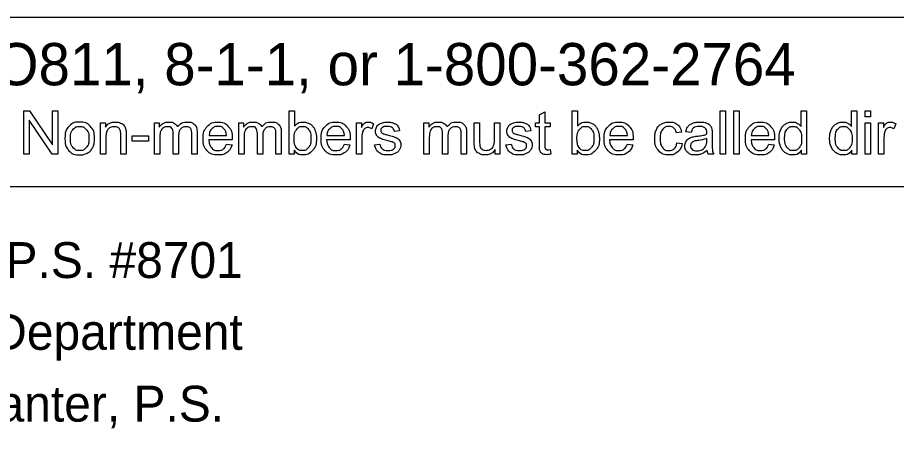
# Model space of a CAD drawing. Extents: x 0 to 34, y 0 to 22.
# Drawn here: x 27.662 to 31.093, y 11.056 to 12.674 of the extents above; entities that cross this region are included whole.
import ezdxf

# ---------------------------------------------------------------- set-up
doc = ezdxf.new("R2010")
doc.units = 0
doc.layers.add('SH_Data', color=7, linetype='Continuous')
doc.layers.add('SH_Text', color=7, linetype='Continuous')

msp = doc.modelspace()

# ---------------------------------------------------------------- linework, layer by layer
at = {"layer": 'SH_Data'}
for p, q in [((32.2439, 12.674), (27.0189, 12.674)), ((32.2439, 12.014), (27.0189, 12.014))]:
    msp.add_line(p, q, dxfattribs=at)
for points in [[(27.6862, 12.1409), (27.6862, 12.3103), (27.7091, 12.3103), (27.7983, 12.1772), (27.7983, 12.3103), (27.8197, 12.3103), (27.8197, 12.1409), (27.7968, 12.1409), (27.7076, 12.2739), (27.7076, 12.1409), (27.6862, 12.1409)], [(28.7416, 12.1409), (28.7224, 12.1409), (28.7224, 12.3103), (28.7431, 12.3103), (28.7431, 12.2499)], [(29.6994, 12.1768), (29.6994, 12.2475), (29.684, 12.2475), (29.684, 12.2637), (29.6994, 12.2637), (29.6994, 12.2941), (29.7202, 12.3065), (29.7202, 12.2637), (29.7409, 12.2637), (29.7409, 12.2475), (29.7202, 12.2475), (29.7202, 12.1756)], [(29.8462, 12.1409), (29.8269, 12.1409), (29.8269, 12.3103), (29.8477, 12.3103), (29.8477, 12.2499)], [(30.4054, 12.1409), (30.4054, 12.3103), (30.4262, 12.3103), (30.4262, 12.1409), (30.4054, 12.1409)], [(30.4579, 12.1409), (30.4579, 12.3103), (30.4787, 12.3103), (30.4787, 12.1409), (30.4579, 12.1409)], [(30.7207, 12.2496), (30.7207, 12.3103), (30.7415, 12.3103), (30.7415, 12.1409), (30.7222, 12.1409)], [(30.918, 12.2496), (30.918, 12.3103), (30.9388, 12.3103), (30.9388, 12.1409), (30.9195, 12.1409)], [(30.9716, 12.2864), (30.9716, 12.3103), (30.9923, 12.3103), (30.9923, 12.2864), (30.9716, 12.2864)], [(27.9863, 12.1409), (27.9863, 12.2637), (28.005, 12.2637), (28.005, 12.2462)], [(28.1966, 12.1409), (28.1966, 12.2637), (28.2152, 12.2637), (28.2152, 12.2463)], [(28.5253, 12.1409), (28.5253, 12.2637), (28.5439, 12.2637), (28.5439, 12.2463)], [(28.9854, 12.1409), (28.9854, 12.2637), (29.0041, 12.2637), (29.0041, 12.2451)], [(29.052, 12.2597), (29.0447, 12.2405)], [(29.2485, 12.1409), (29.2485, 12.2637), (29.2671, 12.2637), (29.2671, 12.2463)], [(29.4451, 12.1876), (29.4451, 12.2637), (29.4659, 12.2637), (29.4659, 12.1956)], [(29.5238, 12.1979), (29.5238, 12.2637), (29.5446, 12.2637), (29.5446, 12.1409), (29.526, 12.1409)], [(30.9716, 12.1409), (30.9716, 12.2637), (30.9923, 12.2637), (30.9923, 12.1409), (30.9716, 12.1409)], [(31.0237, 12.1409), (31.0237, 12.2637), (31.0424, 12.2637), (31.0424, 12.2451)], [(31.0903, 12.2597), (31.0831, 12.2405)], [(28.0859, 12.2163), (28.0859, 12.1409), (28.0652, 12.1409), (28.0652, 12.2155)], [(28.2903, 12.2122), (28.2903, 12.1409), (28.2695, 12.1409), (28.2695, 12.2206)], [(28.363, 12.2251), (28.363, 12.1409), (28.3422, 12.1409), (28.3422, 12.2182)], [(28.619, 12.2122), (28.619, 12.1409), (28.5983, 12.1409), (28.5983, 12.2206)], [(28.6917, 12.2251), (28.6917, 12.1409), (28.6709, 12.1409), (28.6709, 12.2182)], [(29.1535, 12.2319), (29.1331, 12.2292)], [(29.3422, 12.2122), (29.3422, 12.1409), (29.3214, 12.1409), (29.3214, 12.2206)], [(29.4149, 12.2251), (29.4149, 12.1409), (29.3941, 12.1409), (29.3941, 12.2182)], [(29.6663, 12.2319), (29.6459, 12.2292)], [(30.2546, 12.2275), (30.2343, 12.2244)], [(30.2912, 12.2258), (30.2708, 12.2286)], [(30.3736, 12.22), (30.3736, 12.1923)], [(28.0071, 12.2079), (28.0071, 12.1409), (27.9863, 12.1409)], [(28.1096, 12.1918), (28.1096, 12.2127), (28.1736, 12.2127), (28.1736, 12.1918), (28.1096, 12.1918)], [(28.2174, 12.2045), (28.2174, 12.1409), (28.1966, 12.1409)], [(28.4998, 12.1969), (28.4082, 12.1969)], [(28.4094, 12.214), (28.4779, 12.214)], [(28.4777, 12.1805), (28.4992, 12.1778)], [(28.5461, 12.2045), (28.5461, 12.1409), (28.5253, 12.1409)], [(28.9601, 12.1969), (28.8685, 12.1969)], [(28.8697, 12.214), (28.9382, 12.214)], [(28.938, 12.1805), (28.9595, 12.1778)], [(29.0061, 12.2052), (29.0061, 12.1409), (28.9854, 12.1409)], [(29.056, 12.1776), (29.0765, 12.1808)], [(29.2693, 12.2045), (29.2693, 12.1409), (29.2485, 12.1409)], [(29.5688, 12.1776), (29.5894, 12.1808)], [(30.0647, 12.1969), (29.9731, 12.1969)], [(29.9743, 12.214), (30.0428, 12.214)], [(30.0426, 12.1805), (30.0641, 12.1778)], [(30.2361, 12.1858), (30.2565, 12.1831)], [(30.3526, 12.1949), (30.3527, 12.2025)], [(30.617, 12.1969), (30.5255, 12.1969)], [(30.5266, 12.214), (30.5952, 12.214)], [(30.5949, 12.1805), (30.6164, 12.1778)], [(31.0445, 12.2052), (31.0445, 12.1409), (31.0237, 12.1409)], [(28.7416, 12.1563), (28.7416, 12.1409)], [(29.526, 12.1409), (29.526, 12.159)], [(29.7409, 12.1594), (29.7439, 12.141)], [(29.8462, 12.1563), (29.8462, 12.1409)], [(30.7222, 12.1409), (30.7222, 12.1564)], [(30.9195, 12.1409), (30.9195, 12.1564)], [(30.3802, 12.1409), (30.3585, 12.1409)]]:
    msp.add_lwpolyline(points, dxfattribs=at)
for points, degree in [([(27.8469, 12.2023), (27.8469, 12.2364), (27.8659, 12.2528), (27.8817, 12.2664), (27.9045, 12.2664), (27.9298, 12.2664), (27.9458, 12.2498), (27.9619, 12.2332), (27.9619, 12.204), (27.9619, 12.1803), (27.9548, 12.1668), (27.9477, 12.1532), (27.9341, 12.1457), (27.9205, 12.1382), (27.9045, 12.1382), (27.8787, 12.1382), (27.8628, 12.1547), (27.8469, 12.1712), (27.8469, 12.2023)], 3), ([(27.8684, 12.2023), (27.8684, 12.1787), (27.8786, 12.167), (27.8889, 12.1552), (27.9045, 12.1552), (27.9199, 12.1552), (27.9302, 12.167), (27.9404, 12.1788), (27.9404, 12.203), (27.9404, 12.2257), (27.9301, 12.2375), (27.9198, 12.2492), (27.9045, 12.2492), (27.8889, 12.2492), (27.8786, 12.2375), (27.8684, 12.2259), (27.8684, 12.2023)], 3), ([(28.005, 12.2462), (28.0185, 12.2664), (28.044, 12.2664), (28.0551, 12.2664), (28.0644, 12.2624), (28.0737, 12.2584), (28.0783, 12.2519), (28.0829, 12.2455), (28.0848, 12.2366), (28.0859, 12.2308), (28.0859, 12.2163)], 3), ([(28.2152, 12.2463), (28.2209, 12.2554), (28.2305, 12.2609), (28.2401, 12.2664), (28.2524, 12.2664), (28.266, 12.2664), (28.2748, 12.2607), (28.2835, 12.255), (28.2871, 12.2448), (28.3017, 12.2664), (28.325, 12.2664), (28.3433, 12.2664), (28.3532, 12.2563), (28.363, 12.2462), (28.363, 12.2251)], 3), ([(28.4992, 12.1778), (28.4941, 12.159), (28.4804, 12.1486), (28.4666, 12.1382), (28.4452, 12.1382), (28.4183, 12.1382), (28.4026, 12.1547), (28.3868, 12.1713), (28.3868, 12.2012), (28.3868, 12.2322), (28.4027, 12.2493), (28.4187, 12.2664), (28.4441, 12.2664), (28.4687, 12.2664), (28.4843, 12.2496), (28.4999, 12.2329), (28.4999, 12.2025), (28.4999, 12.2006), (28.4998, 12.1969)], 3), ([(28.4779, 12.214), (28.4765, 12.2295), (28.4701, 12.2373), (28.4601, 12.2493), (28.4443, 12.2493), (28.43, 12.2493), (28.4202, 12.2397), (28.4104, 12.2301), (28.4094, 12.214)], 3), ([(28.5439, 12.2463), (28.5497, 12.2554), (28.5593, 12.2609), (28.5689, 12.2664), (28.5811, 12.2664), (28.5948, 12.2664), (28.6035, 12.2607), (28.6122, 12.255), (28.6158, 12.2448), (28.6304, 12.2664), (28.6538, 12.2664), (28.6721, 12.2664), (28.6819, 12.2563), (28.6917, 12.2462), (28.6917, 12.2251)], 3), ([(28.7413, 12.2032), (28.7413, 12.1811), (28.7473, 12.1713), (28.7571, 12.1552), (28.7739, 12.1552), (28.7875, 12.1552), (28.7974, 12.1671), (28.8073, 12.1789), (28.8073, 12.2024), (28.8073, 12.2264), (28.7978, 12.2379), (28.7883, 12.2493), (28.7748, 12.2493), (28.7612, 12.2493), (28.7513, 12.2375), (28.7413, 12.2256), (28.7413, 12.2032)], 3), ([(28.7431, 12.2499), (28.7563, 12.2664), (28.7768, 12.2664), (28.7881, 12.2664), (28.7982, 12.2618), (28.8083, 12.2573), (28.8148, 12.249), (28.8214, 12.2407), (28.825, 12.2291), (28.8287, 12.2174), (28.8287, 12.2041), (28.8287, 12.1726), (28.8131, 12.1554), (28.7975, 12.1382), (28.7757, 12.1382), (28.754, 12.1382), (28.7416, 12.1563)], 3), ([(28.9595, 12.1778), (28.9544, 12.159), (28.9407, 12.1486), (28.9269, 12.1382), (28.9055, 12.1382), (28.8786, 12.1382), (28.8628, 12.1547), (28.8471, 12.1713), (28.8471, 12.2012), (28.8471, 12.2322), (28.863, 12.2493), (28.879, 12.2664), (28.9044, 12.2664), (28.929, 12.2664), (28.9446, 12.2496), (28.9602, 12.2329), (28.9602, 12.2025), (28.9602, 12.2006), (28.9601, 12.1969)], 3), ([(28.9382, 12.214), (28.9368, 12.2295), (28.9304, 12.2373), (28.9204, 12.2493), (28.9046, 12.2493), (28.8903, 12.2493), (28.8805, 12.2397), (28.8707, 12.2301), (28.8697, 12.214)], 3), ([(29.0041, 12.2451), (29.0112, 12.2581), (29.0173, 12.2622), (29.0234, 12.2664), (29.0306, 12.2664), (29.0411, 12.2664), (29.052, 12.2597)], 3), ([(29.1331, 12.2292), (29.1317, 12.2387), (29.125, 12.244), (29.1184, 12.2493), (29.1062, 12.2493), (29.0919, 12.2493), (29.0857, 12.2446), (29.0796, 12.2398), (29.0796, 12.2335), (29.0796, 12.2294), (29.0822, 12.2262), (29.0847, 12.2228), (29.0901, 12.2206), (29.0933, 12.2195), (29.1085, 12.2153), (29.1306, 12.2094), (29.1394, 12.2057), (29.1481, 12.2019), (29.1531, 12.1948), (29.1581, 12.1876), (29.1581, 12.177), (29.1581, 12.1666), (29.152, 12.1574), (29.146, 12.1482), (29.1345, 12.1432), (29.123, 12.1382), (29.1086, 12.1382), (29.0846, 12.1382), (29.072, 12.1481), (29.0595, 12.158), (29.056, 12.1776)], 3), ([(29.0765, 12.1808), (29.0783, 12.1684), (29.0862, 12.1618), (29.0941, 12.1552), (29.1084, 12.1552), (29.1228, 12.1552), (29.1297, 12.1611), (29.1367, 12.1669), (29.1367, 12.1748), (29.1367, 12.1818), (29.1305, 12.1859), (29.1262, 12.1887), (29.1092, 12.1929), (29.0863, 12.1987), (29.0775, 12.2029), (29.0686, 12.2071), (29.064, 12.2146), (29.0595, 12.222), (29.0595, 12.2311), (29.0595, 12.2392), (29.0632, 12.2462), (29.067, 12.2532), (29.0735, 12.2578), (29.0783, 12.2614), (29.0867, 12.2639), (29.0951, 12.2664), (29.1047, 12.2664), (29.1192, 12.2664), (29.1301, 12.2622), (29.1411, 12.2581), (29.1463, 12.2509), (29.1515, 12.2438), (29.1535, 12.2319)], 3), ([(29.2671, 12.2463), (29.2729, 12.2554), (29.2824, 12.2609), (29.292, 12.2664), (29.3043, 12.2664), (29.3179, 12.2664), (29.3267, 12.2607), (29.3354, 12.255), (29.339, 12.2448), (29.3536, 12.2664), (29.3769, 12.2664), (29.3952, 12.2664), (29.4051, 12.2563), (29.4149, 12.2462), (29.4149, 12.2251)], 3), ([(29.6459, 12.2292), (29.6445, 12.2387), (29.6379, 12.244), (29.6312, 12.2493), (29.6191, 12.2493), (29.6047, 12.2493), (29.5986, 12.2446), (29.5925, 12.2398), (29.5925, 12.2335), (29.5925, 12.2294), (29.595, 12.2262), (29.5976, 12.2228), (29.603, 12.2206), (29.6061, 12.2195), (29.6214, 12.2153), (29.6435, 12.2094), (29.6522, 12.2057), (29.661, 12.2019), (29.666, 12.1948), (29.671, 12.1876), (29.671, 12.177), (29.671, 12.1666), (29.6649, 12.1574), (29.6588, 12.1482), (29.6473, 12.1432), (29.6359, 12.1382), (29.6214, 12.1382), (29.5974, 12.1382), (29.5849, 12.1481), (29.5723, 12.158), (29.5688, 12.1776)], 3), ([(29.5894, 12.1808), (29.5911, 12.1684), (29.599, 12.1618), (29.607, 12.1552), (29.6212, 12.1552), (29.6356, 12.1552), (29.6426, 12.1611), (29.6495, 12.1669), (29.6495, 12.1748), (29.6495, 12.1818), (29.6434, 12.1859), (29.6391, 12.1887), (29.6221, 12.1929), (29.5992, 12.1987), (29.5903, 12.2029), (29.5815, 12.2071), (29.5769, 12.2146), (29.5723, 12.222), (29.5723, 12.2311), (29.5723, 12.2392), (29.5761, 12.2462), (29.5798, 12.2532), (29.5863, 12.2578), (29.5912, 12.2614), (29.5996, 12.2639), (29.608, 12.2664), (29.6176, 12.2664), (29.6321, 12.2664), (29.643, 12.2622), (29.6539, 12.2581), (29.6591, 12.2509), (29.6644, 12.2438), (29.6663, 12.2319)], 3), ([(29.8459, 12.2032), (29.8459, 12.1811), (29.8519, 12.1713), (29.8617, 12.1552), (29.8784, 12.1552), (29.8921, 12.1552), (29.902, 12.1671), (29.9119, 12.1789), (29.9119, 12.2024), (29.9119, 12.2264), (29.9024, 12.2379), (29.8929, 12.2493), (29.8794, 12.2493), (29.8658, 12.2493), (29.8558, 12.2375), (29.8459, 12.2256), (29.8459, 12.2032)], 3), ([(29.8477, 12.2499), (29.8609, 12.2664), (29.8813, 12.2664), (29.8927, 12.2664), (29.9028, 12.2618), (29.9129, 12.2573), (29.9194, 12.249), (29.9259, 12.2407), (29.9296, 12.2291), (29.9333, 12.2174), (29.9333, 12.2041), (29.9333, 12.1726), (29.9177, 12.1554), (29.9021, 12.1382), (29.8803, 12.1382), (29.8585, 12.1382), (29.8462, 12.1563)], 3), ([(30.0641, 12.1778), (30.059, 12.159), (30.0452, 12.1486), (30.0315, 12.1382), (30.0101, 12.1382), (29.9832, 12.1382), (29.9674, 12.1547), (29.9517, 12.1713), (29.9517, 12.2012), (29.9517, 12.2322), (29.9676, 12.2493), (29.9836, 12.2664), (30.009, 12.2664), (30.0336, 12.2664), (30.0492, 12.2496), (30.0648, 12.2329), (30.0648, 12.2025), (30.0648, 12.2006), (30.0647, 12.1969)], 3), ([(30.0428, 12.214), (30.0414, 12.2295), (30.035, 12.2373), (30.025, 12.2493), (30.0092, 12.2493), (29.9948, 12.2493), (29.9851, 12.2397), (29.9753, 12.2301), (29.9743, 12.214)], 3), ([(30.2565, 12.1831), (30.2532, 12.162), (30.2393, 12.1501), (30.2255, 12.1382), (30.2054, 12.1382), (30.1802, 12.1382), (30.1649, 12.1546), (30.1496, 12.1711), (30.1496, 12.2018), (30.1496, 12.2217), (30.1562, 12.2366), (30.1628, 12.2515), (30.1762, 12.2589), (30.1897, 12.2664), (30.2056, 12.2664), (30.2256, 12.2664), (30.2383, 12.2563), (30.251, 12.2461), (30.2546, 12.2275)], 3), ([(30.2343, 12.2244), (30.2314, 12.2368), (30.2241, 12.2431), (30.2168, 12.2493), (30.2064, 12.2493), (30.1907, 12.2493), (30.1808, 12.2381), (30.171, 12.2268), (30.171, 12.2024), (30.171, 12.1776), (30.1805, 12.1664), (30.19, 12.1552), (30.2052, 12.1552), (30.2175, 12.1552), (30.2257, 12.1627), (30.2339, 12.1702), (30.2361, 12.1858)], 3), ([(30.3544, 12.156), (30.3428, 12.1462), (30.3321, 12.1422), (30.3214, 12.1382), (30.3092, 12.1382), (30.2889, 12.1382), (30.2781, 12.148), (30.2672, 12.1579), (30.2672, 12.1733), (30.2672, 12.1823), (30.2713, 12.1897), (30.2754, 12.1972), (30.2821, 12.2017), (30.2887, 12.2062), (30.297, 12.2085), (30.3031, 12.2101), (30.3155, 12.2116), (30.3407, 12.2146), (30.3526, 12.2187), (30.3527, 12.223), (30.3527, 12.2242), (30.3527, 12.2369), (30.3468, 12.2421), (30.3389, 12.2492), (30.3232, 12.2492), (30.3085, 12.2492), (30.3016, 12.2441), (30.2946, 12.2389), (30.2912, 12.2258)], 3), ([(30.2708, 12.2286), (30.2736, 12.2416), (30.28, 12.2497), (30.2863, 12.2577), (30.2983, 12.262), (30.3103, 12.2664), (30.3262, 12.2664), (30.3419, 12.2664), (30.3517, 12.2627), (30.3615, 12.259), (30.3661, 12.2534), (30.3707, 12.2478), (30.3726, 12.2392), (30.3736, 12.2339), (30.3736, 12.22)], 3), ([(30.6164, 12.1778), (30.6114, 12.159), (30.5976, 12.1486), (30.5839, 12.1382), (30.5625, 12.1382), (30.5356, 12.1382), (30.5198, 12.1547), (30.504, 12.1713), (30.504, 12.2012), (30.504, 12.2322), (30.52, 12.2493), (30.5359, 12.2664), (30.5613, 12.2664), (30.5859, 12.2664), (30.6015, 12.2496), (30.6171, 12.2329), (30.6171, 12.2025), (30.6171, 12.2006), (30.617, 12.1969)], 3), ([(30.5952, 12.214), (30.5938, 12.2295), (30.5873, 12.2373), (30.5774, 12.2493), (30.5615, 12.2493), (30.5472, 12.2493), (30.5374, 12.2397), (30.5277, 12.2301), (30.5266, 12.214)], 3), ([(30.7222, 12.1564), (30.7106, 12.1382), (30.6879, 12.1382), (30.6732, 12.1382), (30.6609, 12.1463), (30.6486, 12.1543), (30.6418, 12.1688), (30.6351, 12.1833), (30.6351, 12.2022), (30.6351, 12.2205), (30.6412, 12.2355), (30.6473, 12.2504), (30.6595, 12.2584), (30.6718, 12.2664), (30.6869, 12.2664), (30.698, 12.2664), (30.7066, 12.2617), (30.7153, 12.257), (30.7207, 12.2496)], 3), ([(30.6565, 12.2022), (30.6565, 12.1786), (30.6664, 12.1669), (30.6764, 12.1552), (30.6899, 12.1552), (30.7035, 12.1552), (30.7131, 12.1664), (30.7226, 12.1775), (30.7226, 12.2004), (30.7226, 12.2256), (30.7129, 12.2374), (30.7032, 12.2492), (30.689, 12.2492), (30.6751, 12.2492), (30.6658, 12.2379), (30.6565, 12.2265), (30.6565, 12.2022)], 3), ([(30.9195, 12.1564), (30.9078, 12.1382), (30.8852, 12.1382), (30.8705, 12.1382), (30.8582, 12.1463), (30.8459, 12.1543), (30.8391, 12.1688), (30.8324, 12.1833), (30.8324, 12.2022), (30.8324, 12.2205), (30.8385, 12.2355), (30.8446, 12.2504), (30.8568, 12.2584), (30.8691, 12.2664), (30.8842, 12.2664), (30.8952, 12.2664), (30.9039, 12.2617), (30.9125, 12.257), (30.918, 12.2496)], 3), ([(30.8538, 12.2022), (30.8538, 12.1786), (30.8637, 12.1669), (30.8737, 12.1552), (30.8872, 12.1552), (30.9008, 12.1552), (30.9104, 12.1664), (30.9199, 12.1775), (30.9199, 12.2004), (30.9199, 12.2256), (30.9102, 12.2374), (30.9005, 12.2492), (30.8863, 12.2492), (30.8724, 12.2492), (30.8631, 12.2379), (30.8538, 12.2265), (30.8538, 12.2022)], 3), ([(31.0424, 12.2451), (31.0496, 12.2581), (31.0557, 12.2622), (31.0617, 12.2664), (31.069, 12.2664), (31.0795, 12.2664), (31.0903, 12.2597)], 3), ([(28.0652, 12.2155), (28.0652, 12.2282), (28.0627, 12.2345), (28.0603, 12.2408), (28.0541, 12.2446), (28.0479, 12.2483), (28.0396, 12.2483), (28.0263, 12.2483), (28.0167, 12.2399), (28.0071, 12.2314), (28.0071, 12.2079)], 3), ([(28.2695, 12.2206), (28.2695, 12.2344), (28.2644, 12.2414), (28.2593, 12.2483), (28.2478, 12.2483), (28.239, 12.2483), (28.2315, 12.2437), (28.2241, 12.2391), (28.2207, 12.2302), (28.2174, 12.2213), (28.2174, 12.2045)], 3), ([(28.3422, 12.2182), (28.3422, 12.2306), (28.3402, 12.2361), (28.3382, 12.2416), (28.3329, 12.245), (28.3275, 12.2483), (28.3204, 12.2483), (28.3074, 12.2483), (28.2989, 12.2397), (28.2903, 12.2311), (28.2903, 12.2122)], 3), ([(28.5983, 12.2206), (28.5983, 12.2344), (28.5932, 12.2414), (28.5881, 12.2483), (28.5765, 12.2483), (28.5677, 12.2483), (28.5603, 12.2437), (28.5528, 12.2391), (28.5494, 12.2302), (28.5461, 12.2213), (28.5461, 12.2045)], 3), ([(28.6709, 12.2182), (28.6709, 12.2306), (28.6689, 12.2361), (28.6669, 12.2416), (28.6616, 12.245), (28.6563, 12.2483), (28.6491, 12.2483), (28.6361, 12.2483), (28.6276, 12.2397), (28.619, 12.2311), (28.619, 12.2122)], 3), ([(29.0447, 12.2405), (29.0371, 12.245), (29.0295, 12.245), (29.0227, 12.245), (29.0173, 12.2408), (29.0119, 12.2367), (29.0096, 12.2295), (29.0061, 12.2184), (29.0061, 12.2052)], 3), ([(29.3214, 12.2206), (29.3214, 12.2344), (29.3163, 12.2414), (29.3113, 12.2483), (29.2997, 12.2483), (29.2909, 12.2483), (29.2834, 12.2437), (29.276, 12.2391), (29.2726, 12.2302), (29.2693, 12.2213), (29.2693, 12.2045)], 3), ([(29.3941, 12.2182), (29.3941, 12.2306), (29.3921, 12.2361), (29.3901, 12.2416), (29.3848, 12.245), (29.3794, 12.2483), (29.3723, 12.2483), (29.3593, 12.2483), (29.3508, 12.2397), (29.3422, 12.2311), (29.3422, 12.2122)], 3), ([(31.0831, 12.2405), (31.0755, 12.245), (31.0679, 12.245), (31.0611, 12.245), (31.0557, 12.2408), (31.0503, 12.2367), (31.048, 12.2295), (31.0445, 12.2184), (31.0445, 12.2052)], 3), ([(28.4082, 12.1969), (28.4094, 12.1767), (28.4197, 12.166), (28.43, 12.1552), (28.4453, 12.1552), (28.4568, 12.1552), (28.4649, 12.1613), (28.473, 12.1673), (28.4777, 12.1805)], 3), ([(28.8685, 12.1969), (28.8697, 12.1767), (28.88, 12.166), (28.8903, 12.1552), (28.9056, 12.1552), (28.9171, 12.1552), (28.9252, 12.1613), (28.9333, 12.1673), (28.938, 12.1805)], 3), ([(29.526, 12.159), (29.5117, 12.1382), (29.4871, 12.1382), (29.4762, 12.1382), (29.4668, 12.1423), (29.4574, 12.1465), (29.4528, 12.1528), (29.4483, 12.1591), (29.4464, 12.1682), (29.4451, 12.1743), (29.4451, 12.1876)], 3), ([(29.4659, 12.1956), (29.4659, 12.1793), (29.4672, 12.1737), (29.4692, 12.1655), (29.4755, 12.1608), (29.4819, 12.1561), (29.4912, 12.1561), (29.5006, 12.1561), (29.5088, 12.1609), (29.517, 12.1657), (29.5204, 12.174), (29.5238, 12.1822), (29.5238, 12.1979)], 3), ([(29.9731, 12.1969), (29.9743, 12.1767), (29.9845, 12.166), (29.9948, 12.1552), (30.0102, 12.1552), (30.0217, 12.1552), (30.0298, 12.1613), (30.0378, 12.1673), (30.0426, 12.1805)], 3), ([(30.3527, 12.2025), (30.3414, 12.1979), (30.3187, 12.1946), (30.3059, 12.1928), (30.3005, 12.1905), (30.2952, 12.1882), (30.2923, 12.1837), (30.2894, 12.1793), (30.2894, 12.1738), (30.2894, 12.1655), (30.2957, 12.16), (30.302, 12.1544), (30.3141, 12.1544), (30.3261, 12.1544), (30.3355, 12.1597), (30.3448, 12.165), (30.3492, 12.1741), (30.3526, 12.1811), (30.3526, 12.1949)], 3), ([(30.3736, 12.1923), (30.3736, 12.1633), (30.3749, 12.1556), (30.3763, 12.1479), (30.3802, 12.1409)], 3), ([(30.5255, 12.1969), (30.5266, 12.1767), (30.5369, 12.166), (30.5472, 12.1552), (30.5626, 12.1552), (30.574, 12.1552), (30.5821, 12.1613), (30.5902, 12.1673), (30.5949, 12.1805)], 3), ([(29.7439, 12.141), (29.7351, 12.1392), (29.7282, 12.1392), (29.7169, 12.1392), (29.7107, 12.1428), (29.7045, 12.1464), (29.7019, 12.1522), (29.6994, 12.1581), (29.6994, 12.1768)], 3), ([(29.7202, 12.1756), (29.7202, 12.1667), (29.7213, 12.1641), (29.7223, 12.1616), (29.7248, 12.1601), (29.7273, 12.1586), (29.7319, 12.1586), (29.7353, 12.1586), (29.7409, 12.1594)], 3), ([(30.3585, 12.1409), (30.3553, 12.1473), (30.3544, 12.156)], 2)]:
    msp.add_open_spline(points, degree=degree, dxfattribs=at)

# ---------------------------------------------------------------- texts
msp.add_text('OHIO811, 8-1-1, or 1-800-362-2764', height=0.165, dxfattribs=at).set_placement((27.18, 12.4098))
at = {"layer": 'SH_Text'}
for s, p in [('I, hereby certify that this plat is prepared under the direction and supervision of Luke Walker, P.S. #8701 ', (19.9136, 11.6579)), ('for the Ohio Department of Transportation, and is based on a survey performed for the Ohio Department ', (19.9136, 11.3779)), ('of Transportation in September 2020 by Buckley Group under the supervision of Robert C. Canter, P.S. ', (19.9136, 11.0978))]:
    msp.add_text(s, height=0.1400141, dxfattribs=at).set_placement(p)

doc.saveas('drawing.dxf')
